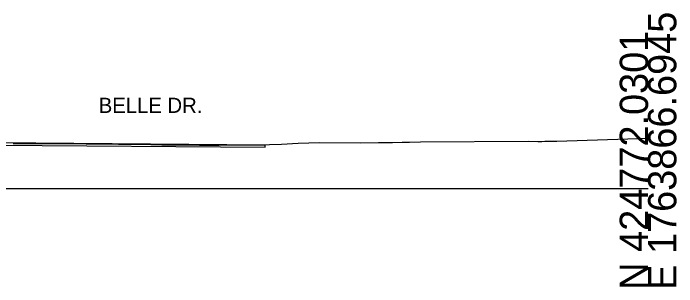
# Model space of a CAD drawing. Extents: x -26 to 3203, y -11010 to 4024.
# Drawn here: x 2137.2 to 2202.8, y 3992.9 to 4019.9 of the extents above; entities that cross this region are included whole.
import ezdxf

# ---------------------------------------------------------------- set-up
doc = ezdxf.new("R2010")
doc.units = 0
for name, color, linetype in [('Exist Cross Section Cell', 7, 'Continuous'), ('Exist XS Ground Line', 7, 'Continuous'), ('Prop CMT Pvmt Course 1', 7, 'Continuous'), ('Prop CMT Pvmt Surface', 7, 'Continuous'), ('Prop XS SE Text', 7, 'Continuous')]:
    doc.layers.add(name, color=color, linetype=linetype)

msp = doc.modelspace()

# ---------------------------------------------------------------- linework, layer by layer
at = {"layer": 'Exist Cross Section Cell'}
msp.add_line((2100, 4002.617), (2200, 4002.617), dxfattribs=at)
at = {"layer": 'Exist XS Ground Line'}
msp.add_lwpolyline([(2137.17, 4007.067), (2138.872, 4007.083), (2140.684, 4007.091), (2140.793, 4007.091), (2141.473, 4007.086), (2143.987, 4007.063), (2144.162, 4007.061), (2144.394, 4007.058), (2146.031, 4007.034), (2147.596, 4007.011), (2147.819, 4007.008), (2148.058, 4007.006), (2150.798, 4006.969), (2151.293, 4006.962), (2151.864, 4006.955), (2154.205, 4006.934), (2155.605, 4006.925), (2156.607, 4006.926), (2157.534, 4006.928), (2158.382, 4006.934), (2159.392, 4006.932), (2160.018, 4006.937), (2160.639, 4006.944), (2161.135, 4006.956), (2162.1, 4006.96), (2162.542, 4006.979), (2163.727, 4007.018), (2165.377, 4007.113), (2167.496, 4007.187), (2171.579, 4007.136), (2173.333, 4007.16), (2174.697, 4007.178), (2175.657, 4007.194), (2176.376, 4007.21), (2177.468, 4007.243), (2188.133, 4007.292), (2189.104, 4007.285), (2189.486, 4007.288), (2189.793, 4007.292), (2190.043, 4007.296), (2190.965, 4007.292), (2200, 4007.612)], dxfattribs=at)
msp.add_lwpolyline([(2137.17, 4007.067), (2138.872, 4007.083), (2140.684, 4007.091), (2140.793, 4007.091), (2141.473, 4007.086), (2143.987, 4007.063), (2144.162, 4007.061), (2144.394, 4007.058), (2146.031, 4007.034), (2147.596, 4007.011), (2147.819, 4007.008), (2148.058, 4007.006), (2150.798, 4006.969), (2151.293, 4006.962), (2151.864, 4006.955), (2154.205, 4006.934), (2155.605, 4006.925), (2156.607, 4006.926), (2157.534, 4006.928), (2158.382, 4006.934), (2159.392, 4006.932), (2160.018, 4006.937), (2160.639, 4006.944), (2161.135, 4006.956), (2162.1, 4006.96), (2162.542, 4006.979), (2163.727, 4007.018), (2165.377, 4007.113), (2167.496, 4007.187), (2171.579, 4007.136), (2173.333, 4007.16), (2174.697, 4007.178), (2175.657, 4007.194), (2176.376, 4007.21), (2177.468, 4007.243), (2188.133, 4007.292), (2189.104, 4007.285), (2189.486, 4007.288), (2189.793, 4007.292), (2190.043, 4007.296), (2190.965, 4007.292), (2200, 4007.612)], dxfattribs=at)
msp.add_lwpolyline([(2137.17, 4007.067), (2138.872, 4007.083), (2140.684, 4007.091), (2140.793, 4007.091), (2141.473, 4007.086), (2143.987, 4007.063), (2144.162, 4007.061), (2144.394, 4007.058), (2146.031, 4007.034), (2147.596, 4007.011), (2147.819, 4007.008), (2148.058, 4007.006), (2150.798, 4006.969), (2151.293, 4006.962), (2151.864, 4006.955), (2154.205, 4006.934), (2155.605, 4006.925), (2156.607, 4006.926), (2157.534, 4006.928), (2158.382, 4006.934), (2159.392, 4006.932), (2160.018, 4006.937), (2160.639, 4006.944), (2161.135, 4006.956), (2162.1, 4006.96), (2162.542, 4006.979), (2163.727, 4007.018), (2165.377, 4007.113), (2167.496, 4007.187), (2171.579, 4007.136), (2173.333, 4007.16), (2174.697, 4007.178), (2175.657, 4007.194), (2176.376, 4007.21), (2177.468, 4007.243), (2188.133, 4007.292), (2189.104, 4007.285), (2189.486, 4007.288), (2189.793, 4007.292), (2190.043, 4007.296), (2190.965, 4007.292), (2200, 4007.612)], dxfattribs=at)
msp.add_lwpolyline([(2137.17, 4007.067), (2138.872, 4007.083), (2140.684, 4007.091), (2140.793, 4007.091), (2141.473, 4007.086), (2143.987, 4007.063), (2144.162, 4007.061), (2144.394, 4007.058), (2146.031, 4007.034), (2147.596, 4007.011), (2147.819, 4007.008), (2148.058, 4007.006), (2150.798, 4006.969), (2151.293, 4006.962), (2151.864, 4006.955), (2154.205, 4006.934), (2155.605, 4006.925), (2156.607, 4006.926), (2157.534, 4006.928), (2158.382, 4006.934), (2159.392, 4006.932), (2160.018, 4006.937), (2160.639, 4006.944), (2161.135, 4006.956), (2162.1, 4006.96), (2162.542, 4006.979), (2163.727, 4007.018), (2165.377, 4007.113), (2167.496, 4007.187), (2171.579, 4007.136), (2173.333, 4007.16), (2174.697, 4007.178), (2175.657, 4007.194), (2176.376, 4007.21), (2177.468, 4007.243), (2188.133, 4007.292), (2189.104, 4007.285), (2189.486, 4007.288), (2189.793, 4007.292), (2190.043, 4007.296), (2190.965, 4007.292), (2200, 4007.612)], dxfattribs=at)
msp.add_lwpolyline([(2137.17, 4007.067), (2138.872, 4007.083), (2140.684, 4007.091), (2140.793, 4007.091), (2141.473, 4007.086), (2143.987, 4007.063), (2144.162, 4007.061), (2144.394, 4007.058), (2146.031, 4007.034), (2147.596, 4007.011), (2147.819, 4007.008), (2148.058, 4007.006), (2150.798, 4006.969), (2151.293, 4006.962), (2151.864, 4006.955), (2154.205, 4006.934), (2155.605, 4006.925), (2156.607, 4006.926), (2157.534, 4006.928), (2158.382, 4006.934), (2159.392, 4006.932), (2160.018, 4006.937), (2160.639, 4006.944), (2161.135, 4006.956), (2162.1, 4006.96), (2162.542, 4006.979), (2163.727, 4007.018), (2165.377, 4007.113), (2167.496, 4007.187), (2171.579, 4007.136), (2173.333, 4007.16), (2174.697, 4007.178), (2175.657, 4007.194), (2176.376, 4007.21), (2177.468, 4007.243), (2188.133, 4007.292), (2189.104, 4007.285), (2189.486, 4007.288), (2189.793, 4007.292), (2190.043, 4007.296), (2190.965, 4007.292), (2200, 4007.612)], dxfattribs=at)
at = {"layer": 'Prop CMT Pvmt Course 1'}
for p, q in [((2135.542, 4006.924), (2162.1, 4006.71)), ((2162.1, 4006.71), (2162.1, 4006.96))]:
    msp.add_line(p, q, dxfattribs=at)
at = {"layer": 'Prop CMT Pvmt Surface'}
msp.add_line((2135.544, 4007.174), (2162.1, 4006.96), dxfattribs=at)

# ---------------------------------------------------------------- texts
at = {"layer": 'Exist Cross Section Cell'}
for s, p in [('E 1763866.6945', (2202.8, 3992.617)), ('N 424772.0301', (2200, 3992.617))]:
    msp.add_text(s, height=2.8, rotation=90, dxfattribs=at).set_placement(p)
at = {"layer": 'Prop XS SE Text'}
msp.add_text('BELLE DR.', height=1.5, rotation=360, dxfattribs=at).set_placement((2145.637, 4010.099))

doc.saveas('drawing.dxf')
